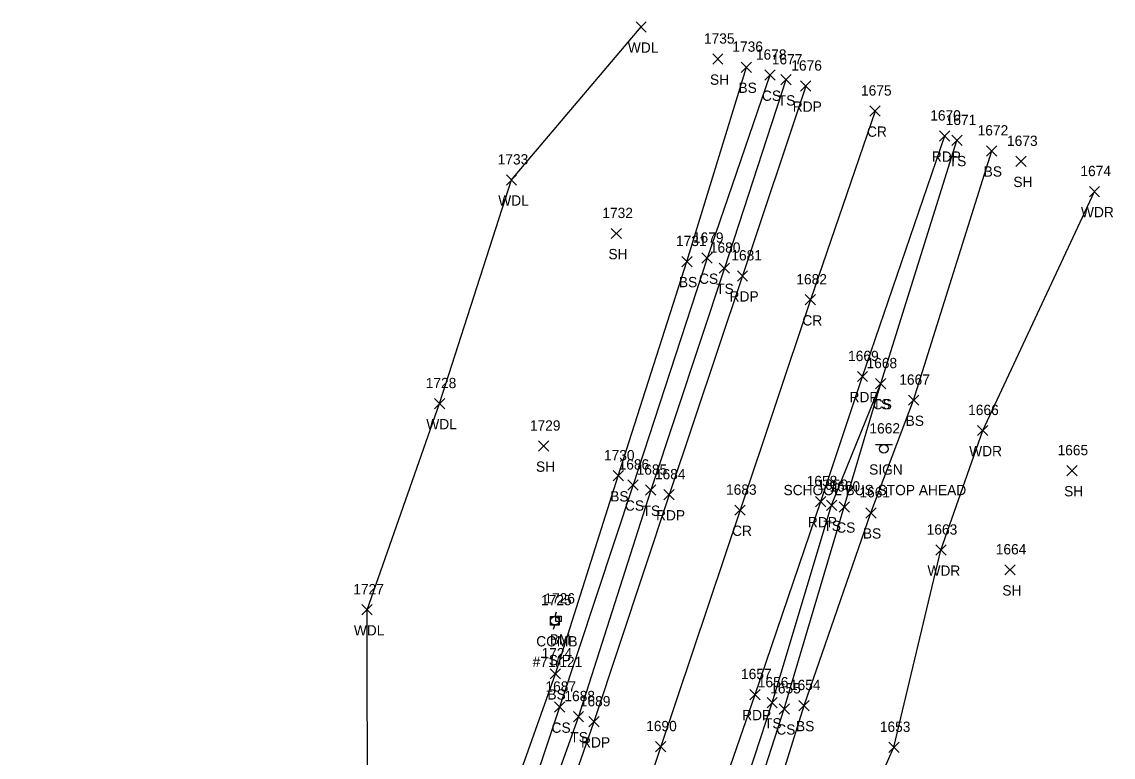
# Model space of a CAD drawing. Extents: x 1654425 to 1656893, y 667839 to 678429.
# Drawn here: x 1654581.9 to 1654794.1, y 668745.6 to 668888.5 of the extents above; entities that cross this region are included whole.
import ezdxf

# ---------------------------------------------------------------- set-up
doc = ezdxf.new("R2010")
doc.units = 0
for name, color, linetype in [('C_A', 7, 'Continuous'), ('C_C', 7, 'Continuous'), ('C_I', 7, 'Continuous'), ('CPBM', 7, 'Continuous'), ('L_A', 7, 'Continuous'), ('L_I', 7, 'Continuous'), ('L_TIC', 7, 'Continuous'), ('LAWA', 7, 'Continuous'), ('LELB', 7, 'Continuous'), ('P_A', 7, 'Continuous'), ('P_I', 7, 'Continuous'), ('P_TIC', 7, 'Continuous'), ('PET', 7, 'Continuous'), ('PRC', 7, 'Continuous'), ('S_A', 7, 'Continuous'), ('S_C', 7, 'Continuous'), ('S_I', 7, 'Continuous'), ('SSGN', 7, 'Continuous'), ('U_A', 7, 'Continuous'), ('U_C', 7, 'Continuous'), ('U_I', 7, 'Continuous'), ('UP', 7, 'Continuous')]:
    doc.layers.add(name, color=color, linetype=linetype)

msp = doc.modelspace()

# ---------------------------------------------------------------- linework, layer by layer
at = {"layer": 'CPBM'}
for p, q in [((1654685.73, 668771.98), (1654685.73, 668772.98)), ((1654685.73, 668772.98), (1654686.73, 668772.98)), ((1654686.23, 668772.48), (1654686.23, 668772.48)), ((1654686.23, 668772.48), (1654686.23, 668772.48)), ((1654686.73, 668772.98), (1654686.73, 668771.98)), ((1654686.73, 668771.98), (1654685.73, 668771.98))]:
    msp.add_line(p, q, dxfattribs=at)
at = {"layer": 'L_TIC'}
for points in [[(1654701.3, 668886.53), (1654703.3, 668888.53)], [(1654703.3, 668886.53), (1654701.3, 668888.53)], [(1654716.2, 668880.29), (1654718.2, 668882.29)], [(1654718.2, 668880.29), (1654716.2, 668882.29)], [(1654721.77, 668878.71), (1654723.77, 668880.71)], [(1654723.77, 668878.71), (1654721.77, 668880.71)], [(1654726.34, 668877.17), (1654728.34, 668879.17)], [(1654728.34, 668877.17), (1654726.34, 668879.17)], [(1654729.44, 668876.26), (1654731.44, 668878.26)], [(1654731.44, 668876.26), (1654729.44, 668878.26)], [(1654762.68, 668864.47), (1654764.68, 668866.47)], [(1654764.68, 668864.47), (1654762.68, 668866.47)], [(1654769.45, 668862.44), (1654771.45, 668864.44)], [(1654771.45, 668862.44), (1654769.45, 668864.44)], [(1654775.17, 668860.41), (1654777.17, 668862.41)], [(1654777.17, 668860.41), (1654775.17, 668862.41)], [(1654676.09, 668856.8), (1654678.09, 668858.8)], [(1654678.09, 668856.8), (1654676.09, 668858.8)], [(1654789.44, 668854.54), (1654791.44, 668856.54)], [(1654791.44, 668854.54), (1654789.44, 668856.54)], [(1654696.45, 668846.39), (1654698.45, 668848.39)], [(1654698.45, 668846.39), (1654696.45, 668848.39)], [(1654710.19, 668840.94), (1654712.19, 668842.94)], [(1654712.19, 668840.94), (1654710.19, 668842.94)], [(1654714.11, 668841.6), (1654716.11, 668843.6)], [(1654716.11, 668841.6), (1654714.11, 668843.6)], [(1654717.47, 668839.65), (1654719.47, 668841.65)], [(1654719.47, 668839.65), (1654717.47, 668841.65)], [(1654747.89, 668817.21), (1654749.89, 668819.21)], [(1654749.89, 668817.21), (1654747.89, 668819.21)], [(1654747.89, 668817.21), (1654749.89, 668819.21)], [(1654749.89, 668817.21), (1654747.89, 668819.21)], [(1654662.1, 668813.33), (1654664.1, 668815.33)], [(1654664.1, 668813.33), (1654662.1, 668815.33)], [(1654754.27, 668813.99), (1654756.27, 668815.99)], [(1654756.27, 668813.99), (1654754.27, 668815.99)], [(1654767.71, 668808.1), (1654769.71, 668810.1)], [(1654769.71, 668808.1), (1654767.71, 668810.1)], [(1654682.36, 668805.07), (1654684.36, 668807.07)], [(1654684.36, 668805.07), (1654682.36, 668807.07)], [(1654785.04, 668800.29), (1654787.04, 668802.29)], [(1654787.04, 668800.29), (1654785.04, 668802.29)], [(1654696.84, 668799.3), (1654698.84, 668801.3)], [(1654698.84, 668799.3), (1654696.84, 668801.3)], [(1654699.71, 668797.51), (1654701.71, 668799.51)], [(1654701.71, 668797.51), (1654699.71, 668799.51)], [(1654703.15, 668796.51), (1654705.15, 668798.51)], [(1654705.15, 668796.51), (1654703.15, 668798.51)], [(1654738.32, 668793.57), (1654740.32, 668795.57)], [(1654740.32, 668793.57), (1654738.32, 668795.57)], [(1654740.78, 668793.23), (1654742.78, 668795.23)], [(1654742.78, 668793.23), (1654740.78, 668795.23)], [(1654745.96, 668792.09), (1654747.96, 668794.09)], [(1654747.96, 668792.09), (1654745.96, 668794.09)], [(1654759.59, 668784.86), (1654761.59, 668786.86)], [(1654761.59, 668784.86), (1654759.59, 668786.86)], [(1654773.03, 668781.02), (1654775.03, 668783.02)], [(1654775.03, 668781.02), (1654773.03, 668783.02)], [(1654648.01, 668773.26), (1654650.01, 668775.26)], [(1654650.01, 668773.26), (1654648.01, 668775.26)], [(1654684.62, 668760.8), (1654686.62, 668762.8)], [(1654686.62, 668760.8), (1654684.62, 668762.8)], [(1654685.43, 668754.34), (1654687.43, 668756.34)], [(1654687.43, 668754.34), (1654685.43, 668756.34)], [(1654726.77, 668755.18), (1654728.77, 668757.18)], [(1654728.77, 668755.18), (1654726.77, 668757.18)], [(1654729.13, 668753.99), (1654731.13, 668755.99)], [(1654731.13, 668753.99), (1654729.13, 668755.99)], [(1654732.96, 668754.64), (1654734.96, 668756.64)], [(1654734.96, 668754.64), (1654732.96, 668756.64)], [(1654689.11, 668752.49), (1654691.11, 668754.49)], [(1654691.11, 668752.49), (1654689.11, 668754.49)], [(1654750.44, 668746.52), (1654752.44, 668748.52)], [(1654752.44, 668746.52), (1654750.44, 668748.52)]]:
    msp.add_lwpolyline(points, dxfattribs=at)
at = {"layer": 'LAWA'}
for points in [[(1654606.2, 668649.8), (1654630.28, 668672.04), (1654637.91, 668695.82), (1654649.06, 668730.98), (1654649.01, 668774.26), (1654663.1, 668814.33), (1654677.09, 668857.8), (1654702.3, 668887.53)], [(1654724.79, 668630.22), (1654704.14, 668642.49), (1654714.45, 668662.63), (1654715.78, 668673.9), (1654734.36, 668709.06), (1654751.44, 668747.52), (1654760.59, 668785.86), (1654768.71, 668809.1), (1654790.44, 668855.54)]]:
    msp.add_lwpolyline(points, dxfattribs=at)
at = {"layer": 'LELB'}
for points in [[(1654581.88, 668581.9), (1654606.98, 668576.45), (1654627.8, 668578.91), (1654641.17, 668616.39), (1654649.87, 668649.23), (1654649.52, 668665.58), (1654651.97, 668671.89), (1654662.51, 668696.29), (1654672.37, 668724.45), (1654685.62, 668761.8), (1654697.84, 668800.3), (1654711.19, 668841.94), (1654722.77, 668879.71)], [(1654727.34, 668878.17), (1654715.11, 668842.6), (1654700.71, 668798.51), (1654686.43, 668755.34), (1654674.1, 668718.36), (1654664.15, 668683.1), (1654653.32, 668648.82)], [(1654730.44, 668877.26), (1654718.47, 668840.65), (1654704.15, 668797.51), (1654690.11, 668753.49), (1654677.29, 668717.55), (1654666.51, 668681.87), (1654655.17, 668648.77)], [(1654723.55, 668624.96), (1654703.53, 668631.69), (1654696.26, 668638.84), (1654692.64, 668643.56), (1654694.36, 668657.38), (1654701.75, 668679), (1654714.03, 668714.19), (1654727.77, 668756.18), (1654739.32, 668794.57), (1654748.89, 668818.21), (1654763.68, 668865.47)], [(1654697.66, 668652.49), (1654702.66, 668663.94), (1654709.94, 668676.92), (1654720.44, 668712.21), (1654733.96, 668755.64), (1654746.96, 668793.09), (1654755.27, 668814.99), (1654770.45, 668863.44)], [(1654703.98, 668677.07), (1654716.75, 668713.56), (1654730.13, 668754.99), (1654741.78, 668794.23), (1654748.89, 668818.21)]]:
    msp.add_lwpolyline(points, dxfattribs=at)
at = {"layer": 'P_TIC'}
for points in [[(1654733.29, 668875.05), (1654735.29, 668877.05)], [(1654735.29, 668875.05), (1654733.29, 668877.05)], [(1654746.78, 668870.19), (1654748.78, 668872.19)], [(1654748.78, 668870.19), (1654746.78, 668872.19)], [(1654760.32, 668865.34), (1654762.32, 668867.34)], [(1654762.32, 668865.34), (1654760.32, 668867.34)], [(1654721, 668838.15), (1654723, 668840.15)], [(1654723, 668838.15), (1654721, 668840.15)], [(1654734.21, 668833.5), (1654736.21, 668835.5)], [(1654736.21, 668833.5), (1654734.21, 668835.5)], [(1654744.33, 668818.59), (1654746.33, 668820.59)], [(1654746.33, 668818.59), (1654744.33, 668820.59)], [(1654706.71, 668795.62), (1654708.71, 668797.62)], [(1654708.71, 668795.62), (1654706.71, 668797.62)], [(1654736.22, 668794.28), (1654738.22, 668796.28)], [(1654738.22, 668794.28), (1654736.22, 668796.28)], [(1654720.54, 668792.61), (1654722.54, 668794.61)], [(1654722.54, 668792.61), (1654720.54, 668794.61)], [(1654723.45, 668756.78), (1654725.45, 668758.78)], [(1654725.45, 668756.78), (1654723.45, 668758.78)], [(1654692.12, 668751.48), (1654694.12, 668753.48)], [(1654694.12, 668751.48), (1654692.12, 668753.48)], [(1654705.09, 668746.66), (1654707.09, 668748.66)], [(1654707.09, 668746.66), (1654705.09, 668748.66)]]:
    msp.add_lwpolyline(points, dxfattribs=at)
at = {"layer": 'PET'}
for points in [[(1654734.29, 668876.05), (1654722, 668839.15), (1654707.71, 668796.62), (1654693.12, 668752.48), (1654680.64, 668716.77), (1654669.36, 668680.84), (1654659.58, 668647.93)], [(1654621.12, 668380.08), (1654629.57, 668415.34), (1654638.69, 668455.31), (1654647.1, 668497.17), (1654655.08, 668532.73), (1654664.14, 668568.47), (1654670.36, 668590.98), (1654672.51, 668598), (1654685.45, 668641.36), (1654697.27, 668678.88), (1654709.65, 668714.91), (1654724.45, 668757.78), (1654737.22, 668795.28), (1654745.33, 668819.59), (1654761.32, 668866.34)]]:
    msp.add_lwpolyline(points, dxfattribs=at)
at = {"layer": 'PRC'}
msp.add_lwpolyline([(1654747.78, 668871.19), (1654735.21, 668834.5), (1654721.54, 668793.61), (1654706.09, 668747.66), (1654694.67, 668713.08), (1654682.21, 668676.37), (1654672.71, 668645.31)], dxfattribs=at)
at = {"layer": 'SSGN'}
for p, q in [((1654747.84, 668806.37), (1654751.17, 668806.37)), ((1654749.48, 668805.54), (1654749.48, 668805.54))]:
    msp.add_line(p, q, dxfattribs=at)
msp.add_circle((1654749.48, 668805.54), 0.833, dxfattribs=at)
at = {"layer": 'UP'}
for p, q in [((1654684.69, 668771.29), (1654684.69, 668772.96)), ((1654684.69, 668772.96), (1654686.35, 668772.96)), ((1654685.77, 668773.79), (1654685.52, 668772.96)), ((1654686.35, 668772.96), (1654686.35, 668771.29)), ((1654686.35, 668771.29), (1654684.69, 668771.29)), ((1654685.27, 668770.46), (1654685.52, 668771.29)), ((1654685.52, 668772.13), (1654685.52, 668772.13))]:
    msp.add_line(p, q, dxfattribs=at)
msp.add_circle((1654685.52, 668772.13), 0.833, dxfattribs=at)

# ---------------------------------------------------------------- texts
at = {"layer": 'C_A'}
msp.add_text('BM', height=2, dxfattribs=at).set_placement((1654684.54, 668767.48))
at = {"layer": 'C_C'}
msp.add_text('SIP', height=2, dxfattribs=at).set_placement((1654684.33, 668763.48))
at = {"layer": 'C_I'}
msp.add_text('1726', height=2, dxfattribs=at).set_placement((1654683.48, 668775.48))
at = {"layer": 'L_A'}
for s, p in [('WDL', (1654699.71, 668882.53)), ('SH', (1654715.68, 668876.29)), ('BS', (1654721.21, 668874.71)), ('CS', (1654725.78, 668873.17)), ('TS', (1654728.85, 668872.26)), ('TS', (1654762.09, 668860.47)), ('BS', (1654768.89, 668858.44)), ('SH', (1654774.66, 668856.41)), ('WDL', (1654674.51, 668852.8)), ('WDR', (1654787.81, 668850.54)), ('SH', (1654695.93, 668842.39)), ('BS', (1654709.63, 668836.94)), ('CS', (1654713.55, 668837.6)), ('TS', (1654716.88, 668835.65)), ('TS', (1654747.3, 668813.21)), ('CS', (1654747.33, 668813.21)), ('WDL', (1654660.52, 668809.33)), ('BS', (1654753.71, 668809.99)), ('WDR', (1654766.07, 668804.1)), ('SH', (1654681.85, 668801.07)), ('SH', (1654784.53, 668796.29)), ('BS', (1654696.28, 668795.3)), ('CS', (1654699.15, 668793.51)), ('TS', (1654702.56, 668792.51)), ('TS', (1654737.73, 668789.57)), ('CS', (1654740.22, 668789.23)), ('BS', (1654745.4, 668788.09)), ('WDR', (1654757.96, 668780.86)), ('SH', (1654772.52, 668777.02)), ('WDL', (1654646.43, 668769.26)), ('BS', (1654684.07, 668756.8)), ('TS', (1654726.18, 668751.18)), ('CS', (1654684.87, 668750.34)), ('CS', (1654728.57, 668749.99)), ('BS', (1654732.4, 668750.64)), ('TS', (1654688.52, 668748.49))]:
    msp.add_text(s, height=2, dxfattribs=at).set_placement(p)
at = {"layer": 'L_I'}
for s, p in [('1735', (1654714.5, 668884.29)), ('1736', (1654720.03, 668882.71)), ('1678', (1654724.6, 668881.17)), ('1677', (1654727.7, 668880.26)), ('1671', (1654761.5, 668868.47)), ('1672', (1654767.71, 668866.44)), ('1673', (1654773.43, 668864.41)), ('1733', (1654674.4, 668860.8)), ('1674', (1654787.7, 668858.54)), ('1732', (1654694.75, 668850.39)), ('1731', (1654709.06, 668844.94)), ('1679', (1654712.36, 668845.6)), ('1680', (1654715.65, 668843.65)), ('1668', (1654746.11, 668821.21)), ('1668', (1654746.11, 668821.21)), ('1728', (1654660.41, 668817.33)), ('1667', (1654752.48, 668817.99)), ('1666', (1654765.87, 668812.1)), ('1729', (1654680.66, 668809.07)), ('1665', (1654783.25, 668804.29)), ('1730', (1654695.06, 668803.3)), ('1686', (1654697.91, 668801.51)), ('1685', (1654701.41, 668800.51)), ('1659', (1654736.57, 668797.57)), ('1660', (1654738.91, 668797.23)), ('1661', (1654744.74, 668796.09)), ('1663', (1654757.81, 668788.86)), ('1664', (1654771.24, 668785.02)), ('1727', (1654646.32, 668777.26)), ('1724', (1654682.93, 668764.8)), ('1687', (1654683.69, 668758.34)), ('1656', (1654724.97, 668759.18)), ('1655', (1654727.39, 668757.99)), ('1654', (1654731.22, 668758.64)), ('1688', (1654687.37, 668756.49)), ('1653', (1654748.7, 668750.52))]:
    msp.add_text(s, height=2, dxfattribs=at).set_placement(p)
at = {"layer": 'P_A'}
for s, p in [('RDP', (1654731.77, 668871.05)), ('CR', (1654746.21, 668866.19)), ('RDP', (1654758.81, 668861.34)), ('RDP', (1654719.49, 668834.15)), ('CR', (1654733.64, 668829.5)), ('RDP', (1654742.81, 668814.59)), ('RDP', (1654705.19, 668791.62)), ('RDP', (1654734.71, 668790.28)), ('CR', (1654719.97, 668788.61)), ('RDP', (1654721.93, 668752.78)), ('RDP', (1654690.61, 668747.48))]:
    msp.add_text(s, height=2, dxfattribs=at).set_placement(p)
at = {"layer": 'P_I'}
for s, p in [('1676', (1654731.49, 668879.05)), ('1675', (1654745.04, 668874.19)), ('1670', (1654758.5, 668869.34)), ('1681', (1654719.83, 668842.15)), ('1682', (1654732.47, 668837.5)), ('1669', (1654742.53, 668822.59)), ('1684', (1654704.97, 668799.62)), ('1658', (1654734.48, 668798.28)), ('1683', (1654718.8, 668796.61)), ('1657', (1654721.71, 668760.78)), ('1689', (1654690.37, 668755.48)), ('1690', (1654703.27, 668750.66))]:
    msp.add_text(s, height=2, dxfattribs=at).set_placement(p)
at = {"layer": 'S_A'}
msp.add_text('SIGN', height=2, dxfattribs=at).set_placement((1654746.62, 668800.52))
at = {"layer": 'S_C'}
msp.add_text('SCHOOL BUS STOP AHEAD', height=2, dxfattribs=at).set_placement((1654729.98, 668796.52))
at = {"layer": 'S_I'}
msp.add_text('1662', height=2, dxfattribs=at).set_placement((1654746.68, 668808.52))
at = {"layer": 'U_A'}
msp.add_text('COMB', height=2, dxfattribs=at).set_placement((1654681.9, 668767.13))
at = {"layer": 'U_C'}
msp.add_text('#71/121', height=2, dxfattribs=at).set_placement((1654681.19, 668763.13))
at = {"layer": 'U_I'}
msp.add_text('1725', height=2, dxfattribs=at).set_placement((1654682.83, 668775.13))

doc.saveas('drawing.dxf')
